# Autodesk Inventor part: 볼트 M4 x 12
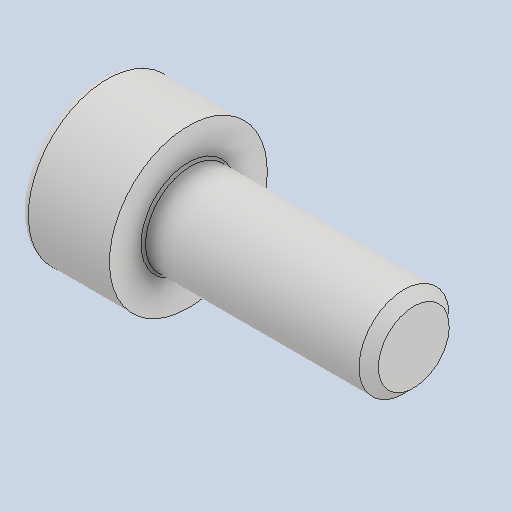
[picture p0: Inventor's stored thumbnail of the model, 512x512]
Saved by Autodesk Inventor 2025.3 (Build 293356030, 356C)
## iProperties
Created: 2025-08
Part Number: 볼트 M4 x 12
Material: 스테인리스강
Description: 6각머리 태핑 나사
Document SubType Name: Modeling
Designer: user
Density: 8.08 g/cm^3
Appearance: 기본값
Sending System: Autodesk Inventor 2026
Preprocessor: ST-DEVELOPER v20.1
Author: jhkim
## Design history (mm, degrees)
sketch "스케치1"
  geometry: 1 further point
  constraints: 1 other
feature "Solid1"
node "솔리드1"
